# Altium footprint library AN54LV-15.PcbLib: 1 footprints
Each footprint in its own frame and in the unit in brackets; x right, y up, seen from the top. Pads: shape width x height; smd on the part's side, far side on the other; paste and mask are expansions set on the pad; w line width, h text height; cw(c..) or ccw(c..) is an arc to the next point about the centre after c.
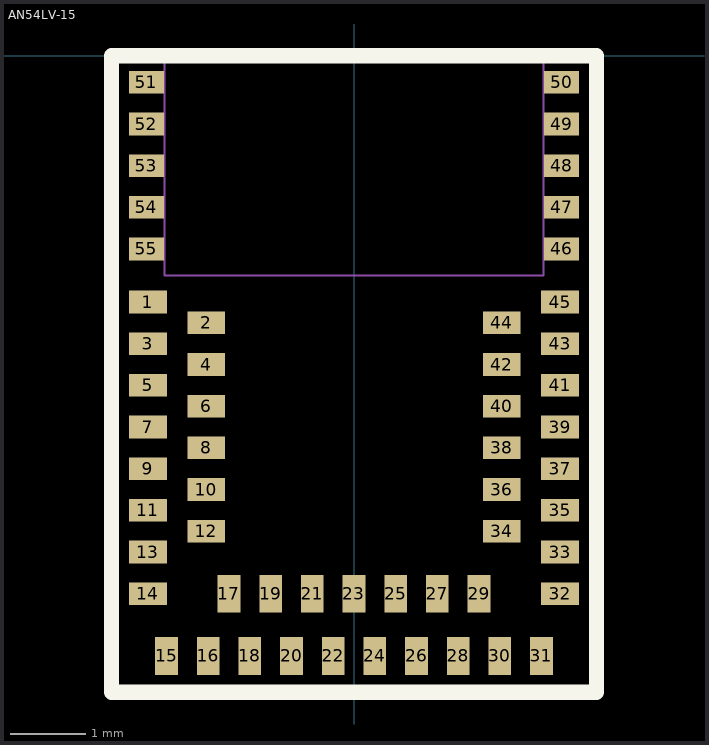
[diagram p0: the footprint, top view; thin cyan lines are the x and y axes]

## AN54LV-15 [mm]
pads (55):
  rect 0.5x0.3 smd mask+0: 1(-2.72,-3.25) 2(-1.95,-3.525) 3(-2.72,-3.8) 4(-1.95,-4.075) 5(-2.72,-4.35) 6(-1.95,-4.625) 7(-2.72,-4.9) 8(-1.95,-5.175) 9(-2.72,-5.45) 10(-1.95,-5.725) 11(-2.72,-6) 12(-1.95,-6.275) 13(-2.72,-6.55) 14(-2.72,-7.1) 32(2.72,-7.1) 33(2.72,-6.55) 34(1.95,-6.275) 35(2.72,-6) 36(1.95,-5.725) 37(2.72,-5.45) 38(1.95,-5.175) 39(2.72,-4.9) 40(1.95,-4.625) 41(2.72,-4.35) 42(1.95,-4.075) 43(2.72,-3.8) 44(1.95,-3.525) 45(2.72,-3.25)
  rect 0.3x0.5 smd mask+0: 15(-2.475,-7.92) 16(-1.925,-7.92) 17(-1.65,-7.1) 18(-1.375,-7.92) 19(-1.1,-7.1) 20(-0.825,-7.92) 21(-0.55,-7.1) 22(-0.275,-7.92) 23(0,-7.1) 24(0.275,-7.92) 25(0.55,-7.1) 26(0.825,-7.92) 27(1.1,-7.1) 28(1.375,-7.92) 29(1.65,-7.1) 30(1.925,-7.92) 31(2.475,-7.92)
  rect 0.46x0.3 smd mask+0: 46(2.74,-2.55) 47(2.74,-2) 48(2.74,-1.45) 49(2.74,-0.9) 50(2.74,-0.35) 51(-2.74,-0.35) 52(-2.74,-0.9) 53(-2.74,-1.45) 54(-2.74,-2) 55(-2.74,-2.55)
Top Overlay:
  lines w0.2: -3.2,-8.4 -3.2,0 3.2,0 3.2,-8.4 -3.2,-8.4
Mechanical 2:
  lines w0.03: -2.5,-2.9 2.5,-2.9 2.5,-0.01 -2.5,-0.01 -2.5,-2.9
  text "No Ground Pad" at -2.261,-1.746 h0.45
Mechanical 9:
  lines w0.01: -3.2,-8.4 3.2,-8.4 3.2,0 -3.2,0 -3.2,-8.4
